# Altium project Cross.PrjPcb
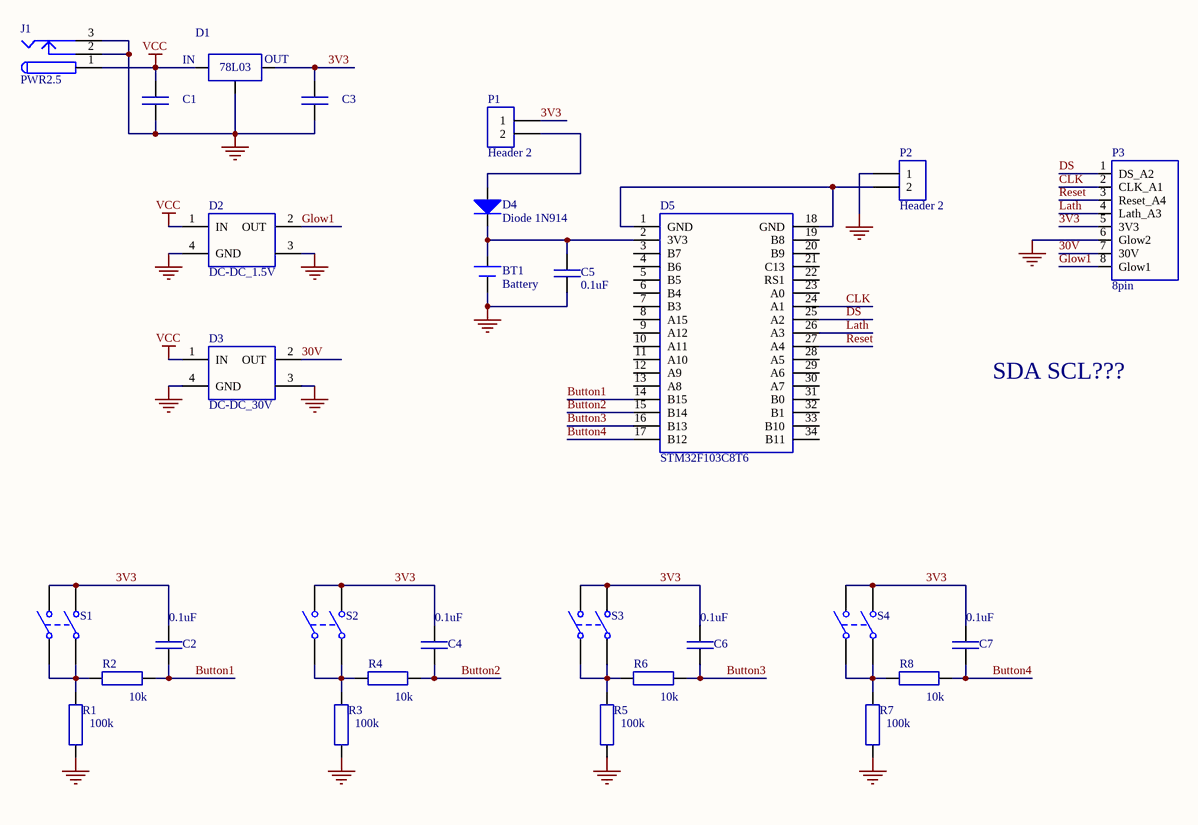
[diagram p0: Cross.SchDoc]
1 sheet, 29 parts. Net scope: global (net labels, ports and power ports of the same name join across sheets).
Board file: Cross.PcbDoc

## Sheet Cross.SchDoc
size A3

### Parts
BT1  Battery  [VBAT]
C1  Capacitor  [C0805]  (value not drawn)
C2  Capacitor  [C0805]  (value not drawn)
C3  Capacitor  [C0805]  (value not drawn)
C4  Capacitor  [C0805]  (value not drawn)
C5  Capacitor  [C0805]  (value not drawn)
C6  Capacitor  [C0805]  (value not drawn)
C7  Capacitor  [C0805]  (value not drawn)
D1  78L03  [SOT89M]  (value not drawn)
D2  DC-DC_1.5V  [DC-DC_1.5V]
D3  DC-DC_30V  [DC-DC_30V]
D4  Diode 1N914  [Diode]
D5  STM32F103C8T6  [STM32F103C8T6_13pins]
J1  PWR2.5  [KLD-0202]
P1  Header 2  [2pin]
P2  Header 2  [2pin]
P3  8pin  [8pin]
R1  Rezistor  [C0805]  (value not drawn)
R2  Rezistor  [C0805]  (value not drawn)
R3  Rezistor  [C0805]  (value not drawn)
R4  Rezistor  [C0805]  (value not drawn)
R5  Rezistor  [C0805]  (value not drawn)
R6  Rezistor  [C0805]  (value not drawn)
R7  Rezistor  [C0805]  (value not drawn)
R8  Rezistor  [C0805]  (value not drawn)
S1  SW-DPST  [DPST-4]  (value not drawn)
S2  SW-DPST  [DPST-4]  (value not drawn)
S3  SW-DPST  [DPST-4]  (value not drawn)
S4  SW-DPST  [DPST-4]  (value not drawn)

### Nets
GND: BT1.2(-) C1.1 C3.1 C5.1 D1.2 D2.3 D2.4(GND) D3.3 D3.4(GND) J1.2 J1.3 P2.1 P3.6(Glow2) R1.1 R3.1 R5.1 R7.1
VCC: C1.2 D1.3 D2.1(IN) D3.1(IN) J1.1
3V3: C2.2 C3.2 C4.2 C6.2 C7.2 D1.1 P1.1 P3.5(3V3) S1.2(NO1) S1.4(NO2) S2.2(NO1) S2.4(NO2) S3.2(NO1) S3.4(NO2) S4.2(NO1) S4.4(NO2)
30V: D3.2(OUT) P3.7(30V)
Button1: C2.1 D5.14(B15) R2.2
Button2: C4.1 D5.15(B14) R4.2
Button3: C6.1 D5.16(B13) R6.2
Button4: C7.1 D5.17(B12) R8.2
CLK: D5.24(A1) P3.2(CLK_A1)
DS: D5.25(A2) P3.1(DS_A2)
Glow1: D2.2(OUT) P3.8(Glow1)
Lath: D5.26(A3) P3.4(Lath_A3)
Reset: D5.27(A4) P3.3(Reset_A4)
NetBT1_1: BT1.1(+) C5.2 D4.2(K) D5.2(3V3)
NetD4_1: D4.1(A) P1.2
NetD5_1: D5.1(GND) D5.18(GND) P2.2
NetR1_2: R1.2 R2.1 S1.1(COMMON1) S1.3(COMMON2)
NetR3_2: R3.2 R4.1 S2.1(COMMON1) S2.3(COMMON2)
NetR5_2: R5.2 R6.1 S3.1(COMMON1) S3.3(COMMON2)
NetR7_2: R7.2 R8.1 S4.1(COMMON1) S4.3(COMMON2)

Not connected (* = marked no-connect by the designer): D5 3(B7) 4(B6) 5(B5) 6(B4) 7(B3) 8(A15) 9(A12) 10(A11) 11(A10) 12(A9) 13(A8) 19(B8) 20(B9) 21(C13) 22(RS1) 23(A0) 28(A5) 29(A6) 30(A7) 31(B0) 32(B1) 33(B10) 34(B11)

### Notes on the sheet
- (near C5) 0.1uF
- SDA SCL???
- (near C2) 0.1uF
- (near C4) 0.1uF
- (near C6) 0.1uF
- (near C7) 0.1uF
- (near R2) 10k
- (near R4) 10k
- (near R6) 10k
- (near R8) 10k
- (near R1) 100k
- (near R3) 100k
- (near R5) 100k
- (near R7) 100k

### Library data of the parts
BT1 = Battery: Multicell Battery
D1 = 78L03: Note: Pin 2 is not connected and not drawn.
D4 = Diode 1N914: High Conductance Fast Diode
J1 = PWR2.5: Low Voltage Power Supply Connector
P1 P2 = Header 2: Header, 2-Pin
S1-S4 = SW-DPST: Double-Pole, Single-Throw Switch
